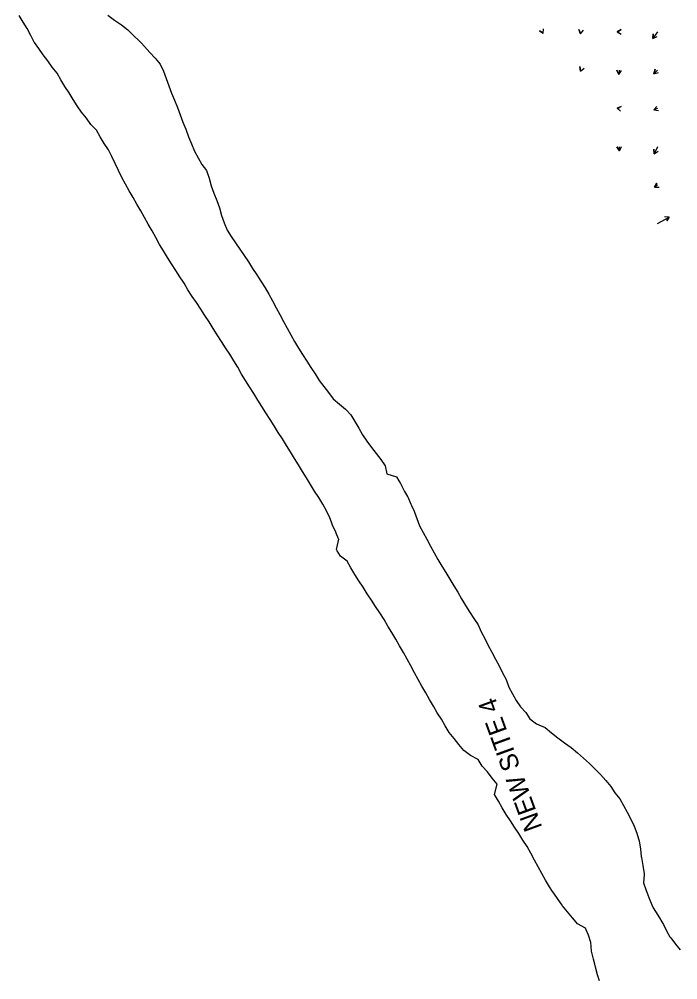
# Model space of a CAD drawing. Extents: x 954385 to 988206, y 1868364 to 1924553.
# Drawn here: x 955775 to 956634, y 1920383 to 1921635 of the extents above; entities that cross this region are included whole.
import ezdxf

# ---------------------------------------------------------------- set-up
doc = ezdxf.new("R2010")
doc.units = 0
for name, color, linetype in [('14', 7, 'Continuous'), ('24', 7, 'Continuous'), ('26', 7, 'Continuous')]:
    doc.layers.add(name, color=color, linetype=linetype)

msp = doc.modelspace()

# ---------------------------------------------------------------- linework, layer by layer
at = {"layer": '24'}
for points in [[(956531.6, 1920381.8), (956528.8, 1920389.4), (956526.2, 1920399.6), (956525.2, 1920403.5), (956523.6, 1920409.8), (956521.2, 1920420.1), (956520.5, 1920426.4), (956520.2, 1920431.4), (956517.2, 1920441.3), (956514, 1920448.1), (956513, 1920450.5), (956502.9, 1920456), (956496.8, 1920463.2), (956496.3, 1920463.8), (956489.6, 1920471.5), (956483.3, 1920479.4), (956482.7, 1920480.2), (956477.4, 1920487.5), (956471.8, 1920495.9), (956470.2, 1920498.2), (956466.4, 1920504.3), (956461.1, 1920512.8), (956456.1, 1920521.5), (956451.3, 1920530.2), (956446.5, 1920539), (956441.8, 1920547.9), (956437.1, 1920556.8), (956431.6, 1920565.1), (956426.1, 1920573.5), (956420.8, 1920581.9), (956415.3, 1920590.3), (956409.8, 1920598.7), (956404.4, 1920607.1), (956399.5, 1920615.8), (956394.7, 1920624.6), (956397.8, 1920638.2), (956391.4, 1920646), (956385.3, 1920654), (956378.5, 1920661.6), (956373.4, 1920670.1), (956363.1, 1920675.6), (956354.4, 1920682), (956347.9, 1920689.7), (956341.7, 1920697.7), (956335.4, 1920705.5), (956330.2, 1920714.1), (956325.2, 1920722.8), (956319.9, 1920731.2), (956314.9, 1920739.9), (956309.9, 1920748.5), (956304.8, 1920757.2), (956299.6, 1920765.7), (956294.9, 1920774.5), (956290.2, 1920783.4), (956285.5, 1920792.2), (956280.6, 1920801), (956275.7, 1920809.7), (956270.7, 1920818.3), (956265.7, 1920827), (956260.6, 1920835.6), (956255.5, 1920844.2), (956250.5, 1920852.9), (956245.1, 1920861.3), (956239.3, 1920869.5), (956234, 1920877.9), (956228.6, 1920886.4), (956223.1, 1920894.7), (956217.5, 1920903), (956212.2, 1920911.5), (956207.1, 1920920.1), (956202.2, 1920928.8), (956193.6, 1920935.3), (956189.4, 1920942.1), (956188.4, 1920943.8), (956191.3, 1920957.4), (956191.2, 1920957.9), (956188.2, 1920965.3), (956187.5, 1920966.7), (956183.3, 1920975.9), (956181.9, 1920979.6), (956179.8, 1920985.5), (956175.4, 1920994.5), (956170.4, 1921003.2), (956165.2, 1921011.7), (956159.9, 1921020.2), (956154.7, 1921028.7), (956149.5, 1921037.3), (956144.2, 1921045.8), (956138.9, 1921054.3), (956133.6, 1921062.7), (956128.4, 1921071.3), (956123.3, 1921079.5), (956117.8, 1921088.2), (956112.5, 1921096.7), (956107.1, 1921105.1), (956101.8, 1921113.6), (956096.4, 1921122), (956091.1, 1921130.5), (956085.7, 1921138.9), (956080.4, 1921147.4), (956075.1, 1921155.9), (956069.8, 1921164.3), (956064.5, 1921172.8), (956059.7, 1921181.6), (956054.4, 1921190.1), (956049.1, 1921198.6), (956043.7, 1921207), (956038.3, 1921215.4), (956032.8, 1921223.8), (956027.5, 1921232.3), (956022.3, 1921240.8), (956016.8, 1921249.2), (956011.3, 1921257.5), (956006, 1921266), (956000.1, 1921274.1), (955994.7, 1921282.6), (955989.6, 1921291.1), (955984.2, 1921299.6), (955978.8, 1921308), (955973.4, 1921316.4), (955968, 1921324.8), (955962.7, 1921333.3), (955957.6, 1921341.9), (955952.9, 1921350.7), (955947.8, 1921359.3), (955942.7, 1921368), (955937.9, 1921376.7), (955933, 1921385.4), (955928, 1921394.1), (955923, 1921402.8), (955918.1, 1921411.5), (955913.2, 1921420.2), (955908.3, 1921429), (955903.9, 1921438), (955899.9, 1921447.3), (955895.6, 1921456.4), (955891.1, 1921465.3), (955885.4, 1921473.6), (955880, 1921482), (955875.4, 1921490.9), (955868.1, 1921498.2), (955862.5, 1921506.5), (955855.9, 1921514.1), (955850.3, 1921522.4), (955844.9, 1921530.9), (955839.7, 1921539.4), (955834.3, 1921547.8), (955829, 1921556.3), (955824.2, 1921565.1), (955817.7, 1921572.8), (955811.8, 1921581), (955806, 1921589.1), (955800.1, 1921597.2), (955794.4, 1921605.1), (955794.2, 1921605.4), (955789.8, 1921614.4), (955785, 1921623.2), (955779.8, 1921631.7), (955774.6, 1921640.2)], [(955890, 1921640.5), (955899, 1921634.3), (955908.1, 1921628.1), (955916.3, 1921621.4), (955923.7, 1921614.3), (955931.1, 1921607.1), (955934, 1921604.1), (955938.2, 1921599.7), (955945, 1921592.1), (955951.7, 1921584.5), (955958.6, 1921577), (955962.8, 1921567.8), (955966.2, 1921558.2), (955969.6, 1921548.6), (955973.3, 1921539.1), (955977.1, 1921529.7), (955980.9, 1921520.3), (955984.6, 1921510.9), (955988.2, 1921501.3), (955991.9, 1921491.9), (955995.3, 1921482.2), (955999.2, 1921472.9), (956003.3, 1921463.6), (956008.2, 1921454.9), (956012.9, 1921446.1), (956019, 1921438.1), (956022.2, 1921428.3), (956024.8, 1921418.2), (956028.6, 1921408.8), (956032.2, 1921399.2), (956035.7, 1921389.7), (956038.3, 1921379.5), (956042, 1921370.1), (956045.7, 1921360.6), (956051, 1921352.2), (956056.8, 1921344), (956062.4, 1921335.7), (956068, 1921327.4), (956073.5, 1921319.1), (956079, 1921310.6), (956084.4, 1921302.2), (956089.8, 1921293.8), (956095.2, 1921285.4), (956100.3, 1921276.8), (956105.1, 1921268.1), (956109.8, 1921259.2), (956114.4, 1921250.3), (956119.1, 1921241.5), (956124, 1921232.7), (956128.8, 1921223.9), (956133.8, 1921215.2), (956139, 1921206.7), (956144.2, 1921198.2), (956149.6, 1921189.7), (956155, 1921181.3), (956160.4, 1921172.9), (956165.8, 1921164.5), (956171.8, 1921156.4), (956178.2, 1921148.6), (956183.9, 1921140.4), (956192.2, 1921133.7), (956200.2, 1921126.9), (956200.4, 1921126.7), (956207, 1921119.4), (956212.5, 1921111), (956217.5, 1921102.3), (956222.4, 1921093.6), (956228, 1921085.3), (956234, 1921077.2), (956240.2, 1921069.3), (956246.1, 1921061.2), (956251.7, 1921052.9), (956254.1, 1921042.7), (956266.6, 1921038.6), (956269.9, 1921033.5), (956271.7, 1921030), (956276.4, 1921021.2), (956277.2, 1921019.8), (956281.2, 1921013), (956281.5, 1921012.5), (956285.4, 1921003.2), (956286.2, 1921001.3), (956289.6, 1920994), (956293.1, 1920984.5), (956296.6, 1920974.9), (956301.5, 1920966.2), (956306.3, 1920957.4), (956310.9, 1920948.5), (956315.6, 1920939.6), (956320.7, 1920931), (956325.9, 1920922.5), (956331.1, 1920913.9), (956336.4, 1920905.4), (956341.5, 1920896.8), (956346.5, 1920888.2), (956351.6, 1920879.6), (956356.7, 1920871), (956362.1, 1920862.6), (956367.4, 1920854.1), (956373.1, 1920845.9), (956377.2, 1920836.6), (956381.9, 1920827.8), (956386.4, 1920818.8), (956391.2, 1920810), (956395.9, 1920801.2), (956400.4, 1920792.2), (956405, 1920783.3), (956409.5, 1920774.3), (956413, 1920764.7), (956417.9, 1920756), (956422.7, 1920747.3), (956428.2, 1920738.9), (956435.2, 1920731.4), (956440.7, 1920723.1), (956449.3, 1920716.6), (956460.7, 1920711.9), (956468.8, 1920705.1), (956477, 1920698.4), (956485.8, 1920692.1), (956494.6, 1920685.7), (956502.9, 1920679.1), (956510.7, 1920672.1), (956518.2, 1920665), (956525.6, 1920657.8), (956532.9, 1920650.5), (956539.5, 1920642.8), (956546.2, 1920635.2), (956551.5, 1920626.7), (956557.8, 1920618.9), (956562.8, 1920610.2), (956567.7, 1920601.5), (956572.4, 1920592.6), (956576.5, 1920583.4), (956580.2, 1920574), (956582.3, 1920566.8), (956583, 1920564), (956584.9, 1920553.5), (956585.9, 1920543.6), (956586.1, 1920542.6), (956588.1, 1920532.1), (956589.5, 1920521.3), (956589.6, 1920520.4), (956588.9, 1920509.2), (956592.2, 1920499.6), (956593.1, 1920497.1), (956595.8, 1920490.1), (956599.7, 1920480.8), (956601.3, 1920476.7), (956604.3, 1920471.9), (956609.9, 1920463.7), (956612.9, 1920458.4), (956614.8, 1920455), (956619.3, 1920446.1), (956623.1, 1920439.1), (956623.2, 1920439.1), (956624.4, 1920437.5), (956630.5, 1920429.6), (956636.6, 1920422)]]:
    msp.add_lwpolyline(points, dxfattribs=at)
at = {"layer": '26'}
for points in [[(956457.1, 1921618.9), (956458.1, 1921617.1), (956453, 1921620.2), (956458.1, 1921617.1), (956458.2, 1921623.1)], [(956507.1, 1921618.9), (956506.8, 1921616.4), (956504.5, 1921621.9), (956506.8, 1921616.4), (956510.5, 1921621.1)], [(956557.1, 1921618.9), (956554.6, 1921618.9), (956559.8, 1921622), (956554.6, 1921618.9), (956559.9, 1921616)], [(956607.1, 1921618.9), (956601, 1921610.3), (956601.6, 1921616.3), (956601, 1921610.3), (956606.5, 1921612.8)], [(956507.1, 1921568.9), (956506.7, 1921567.8), (956505.7, 1921573.8), (956506.7, 1921567.8), (956511.4, 1921571.7)], [(956557.1, 1921568.9), (956556.7, 1921563.5), (956554.1, 1921568.9), (956556.7, 1921563.5), (956560.1, 1921568.5)], [(956607.1, 1921568.9), (956602.5, 1921564.3), (956604, 1921570.1), (956602.5, 1921564.3), (956608.3, 1921565.8)], [(956557.1, 1921518.9), (956554.3, 1921519.4), (956559.8, 1921521.6), (956554.3, 1921519.4), (956559, 1921515.6)], [(956607.1, 1921518.9), (956602.5, 1921517.3), (956606.4, 1921521.8), (956602.5, 1921517.3), (956608.4, 1921516.2)], [(956557.1, 1921468.9), (956557.4, 1921464), (956554.1, 1921469), (956557.4, 1921464), (956560.1, 1921469.3)], [(956607.1, 1921468.9), (956602.8, 1921460), (956602.4, 1921466), (956602.8, 1921460), (956607.8, 1921463.4)], [(956607.1, 1921418.9), (956603.2, 1921416.6), (956606.1, 1921421.8), (956603.2, 1921416.6), (956609.2, 1921416.6)], [(956607.1, 1921368.9), (956622.2, 1921377.5), (956619.2, 1921372.4), (956622.2, 1921377.5), (956616.2, 1921377.6)]]:
    msp.add_lwpolyline(points, dxfattribs=at)

# ---------------------------------------------------------------- texts
at = {"layer": '14'}
msp.add_text('NEW SITE 4', height=24, rotation=110, dxfattribs=at).set_placement((956457.1, 1920581.7))

doc.saveas('drawing.dxf')
